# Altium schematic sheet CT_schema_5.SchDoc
size 218 x 258 mm
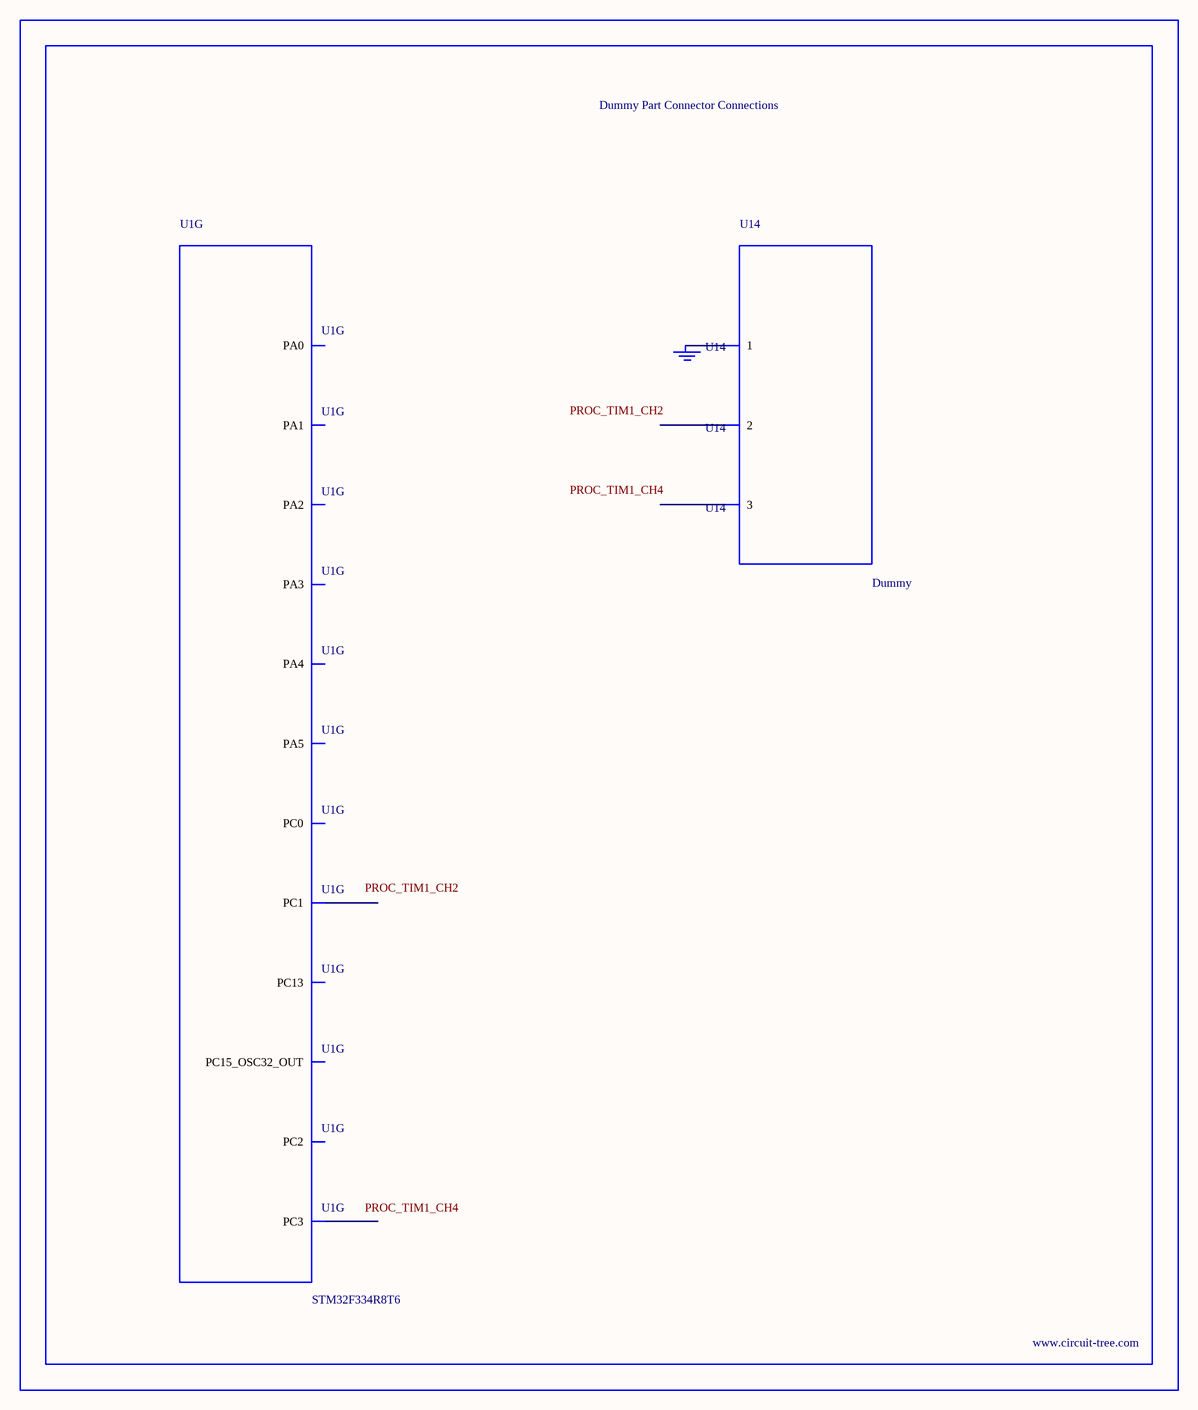
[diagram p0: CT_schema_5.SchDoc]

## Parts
BORDER4  (no value)
GND_INSTANCE_4_0  (no value)
U1  STM32F334R8T6  [LQFP64]  (part G of 7)
U14  Dummy  [DUMMY_PACKAGE_126]

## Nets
NetGND_INSTANCE_4_0_0: GND_INSTANCE_4_0.0(GND) U14.1

Not connected (* = marked no-connect by the designer): U1 2(PC13) 4(PC15_OSC32_OUT) 8(PC0) 9(PC1) 10(PC2) 11(PC3) 14(PA0) 15(PA1) 16(PA2) 17(PA3) 20(PA4) 21(PA5); U14 2 3

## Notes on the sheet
- Labels drawn without touching a wire or pin: PROC_TIM1_CH2, PROC_TIM1_CH4

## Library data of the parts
BORDER4 = BORDER_PAGE4
GND_INSTANCE_4_0 = GND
